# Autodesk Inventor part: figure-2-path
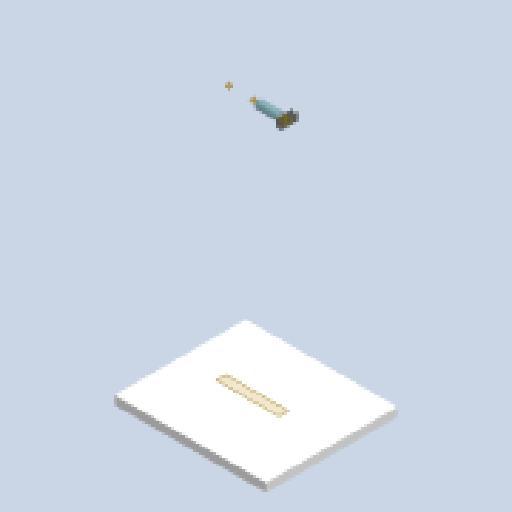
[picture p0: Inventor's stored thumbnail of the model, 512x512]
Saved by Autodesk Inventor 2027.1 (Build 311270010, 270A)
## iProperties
Created: 2026-09
Part Number: figure-2-path
Material: Generic
Document SubType Name: Modeling
Designer: dunge
Density: 1 g/cm^3
Appearance: Default
Author: dunge
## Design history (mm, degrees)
sketch "GRIN-sketch"
  geometry: L1 (0, 0)-(-73.025, 0); L2 (-73.025, -3.175)-(-73.025, 3.175); L3 (-73.025, 3.175)-(-92.075, -7.62); L4 (-92.075, -7.62)-(-92.075, 7.62); L5 (-92.075, 7.62)-(-73.025, -3.175); L6 (-73.025, 0)-(-92.075, 0); L7 (-92.075, 7.62)-(-90.805, 7.62); L8 (-90.805, 7.62)-(-90.805, 12.7); L9 (-90.805, 12.7)-(-154.305, 12.7); L10 (-154.305, 12.7)-(-154.305, 7.62); L11 (-154.305, 7.62)-(-153.035, 7.62); L12 (-153.035, 7.62)-(-153.035, 0); L13 (-153.035, 0)-(-92.075, 0); 3 further points
  constraints: 27 end point, 5 perpendicular, 5 point on line, 2 horizontal, 2 midpoint, 1 parallel, 1 vertical
  dimensions: "d0" = 73.025 distance of L1.end L1.start; "d1" = 6.35 distance of L2.start L2.end; "d3" = 1.27 distance of L4.end L7.end; "d4" = 1.27 distance of L10.end L11.end; "d5" = 12.7 distance between parallel lines of L13 L9; "d6" = 63.5 distance of L8.end L9.end; "d7" = 15.24 distance of L3.end L4.end; "d8" = 19.05 distance of L1.end L6.end
workpoint "Work Point1"
workpoint "Work Point2"
revolve "Revolution1" stored, may be unused: angle "d2" = 360 deg
workpoint "Work Point3"
revolve "Revolution2" stored, may be unused: angle "d9" = 360 deg
workplane "Work Plane1"
sketch "Sketch2"
  geometry: L1 (135.016, 204.838)-(-317.177, 204.838); L2 (-317.177, 204.838)-(-317.177, -186.688); L3 (-317.177, -186.688)-(135.016, -186.688); L4 (135.016, -186.688)-(135.016, 204.838); 1 further point
  constraints: 8 end point, 2 parallel, 1 horizontal, 1 perpendicular
extrude "Extrusion1" new body sketch "Sketch2" distance "d11" = 25.4; taper "d12" = 0 deg
sketch "Sketch3"
  geometry: L1 (-153.035, -7.62)-(-153.035, 7.62) reference; L2 (-153.035, 7.62)-(-165.735, 0); L3 (-165.735, 0)-(-153.035, 0); 1 further point
  constraints: 4 end point, 1 horizontal, 1 midpoint
  dimensions: "d13" = 12.7 distance of L2.end L3.end
revolve "Revolution3" sketch "Sketch3" stored, may be unused: angle "d14" = 360 deg
sketch "red-side-beam-sketch"
  geometry: L1 (-153.035, -7.62)-(-153.035, 7.62) reference; L2 (-153.035, 7.62)-(-165.735, -2.54); L3 (-165.735, -2.54)-(-150.285, -7.62); L4 (-165.735, -2.54)-(-151.66, 0); L5 (-151.66, 0)-(-153.035, 7.62); L6 (-151.66, 0)-(-150.285, -7.62); L7 (-165.735, 0)-(-153.035, 7.62) reference; L8 (-165.735, 0)-(-153.035, -7.62) reference; 1 further point
  constraints: 10 end point, 2 perpendicular, 1 collinear, 1 horizontal alignment, 1 vertical alignment
  dimensions: "d15" = 2.54 distance of L7.start L2.end
revolve "Revolution4" sketch "red-side-beam-sketch" stored, may be unused: angle "d16" = 360 deg
workplane "Work Plane2"
sketch "Sketch5"
  geometry: L1 (25.4, -12.7)-(-25.4, -12.7); L2 (-25.4, -12.7)-(-25.4, 12.7); L3 (-25.4, 12.7)-(25.4, 12.7); L4 (25.4, 12.7)-(25.4, -12.7); L5 (25.4, -12.7)-(-25.4, 12.7); L6 (-25.4, -12.7)-(25.4, 12.7); 1 further point
  constraints: 12 end point, 2 midpoint, 2 parallel, 1 horizontal, 1 perpendicular
  dimensions: "d23" = 25.4 distance of L1.end L2.end; "d24" = 50.8 distance of L2.end L3.end
extrude "Extrusion2" new body sketch "Sketch5" distance "d18" = 1.27; taper "d19" = 0 deg
workplane "Work Plane3"
sketch "Sketch6"
  geometry: L1 (-25.4, 12.7)-(25.4, 12.7) reference; L2 (25.4, 12.7)-(25.4, -12.7) reference; L3 (25.4, -12.7)-(-25.4, -12.7) reference; L4 (-25.4, -12.7)-(-25.4, 12.7) reference; 2 further points
extrude "Extrusion3" new body sketch "Sketch6" distance "d21" = 1.27; taper "d22" = 0 deg
sketch "Sketch7"
  geometry: L1 (-165.735, 0)-(-153.035, 7.62) reference; L2 (-153.035, 7.62)-(-178.435, 0); L3 (-178.435, -25.4)-(-178.435, 25.4) reference; L4 (-153.035, -7.62)-(-153.035, 7.62) reference; L5 (-153.035, 0)-(-153.035, 7.62); L6 (-178.435, 0)-(-153.035, 0); L7 (-150.285, -7.62)-(-153.035, 7.62) reference; L8 (-153.035, 7.62)-(-153.035, 0); 2 further points
  constraints: 8 end point, 2 collinear, 2 midpoint, 1 horizontal, 1 point on line
revolve "Revolution5" sketch "Sketch7" stored, may be unused: angle "d25" = 360 deg
node "red-beam"
node "Finishes"
node "GRIN"
node "white-background"
node "green-beam"
node "red-side-beam"
node "black-plante-near"
node "black-plane-far"
node "extra-red-beam"
node "Finish1" dims "Finish1_Area" = 64.83201
node "Finish2" dims "Finish2_Area" = 620.20995
node "Finish3" dims "Finish3_Area" = 17704.58546
node "Finish4" dims "Finish4_Area" = 53.69651
node "Finish5" dims "Finish5_Area" = 140.12218
node "Finish6" dims "Finish6_Area" = 554.8376
node "Finish7" dims "Finish7_Area" = 18.24147
node "Finish8" dims "Finish8_Area" = 18.24147
node "Finish9" dims "Finish9_Area" = 81.72365
other parameters: "d10" = -762, "d17" = -12.7, "d20" = -12.7
